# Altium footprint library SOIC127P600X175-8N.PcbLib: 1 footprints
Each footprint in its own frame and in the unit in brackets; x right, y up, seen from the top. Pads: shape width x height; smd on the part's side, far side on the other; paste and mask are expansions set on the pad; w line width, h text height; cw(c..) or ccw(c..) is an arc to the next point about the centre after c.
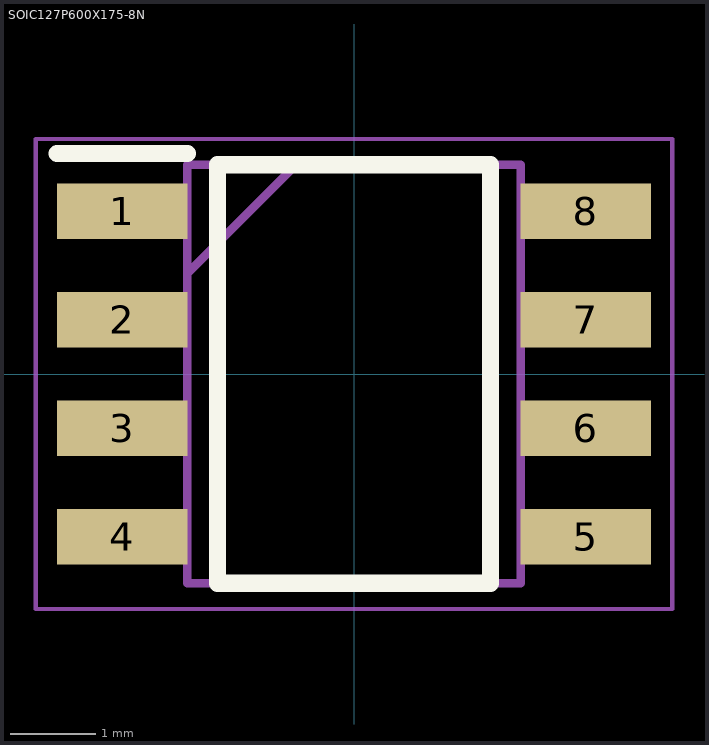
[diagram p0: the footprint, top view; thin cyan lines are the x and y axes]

## SOIC127P600X175-8N [mm]
pads (8):
  rect 1.525x0.65 smd: 1(-2.712,1.905) 2(-2.712,0.635) 3(-2.712,-0.635) 4(-2.712,-1.905) 5(2.712,-1.905) 6(2.712,-0.635) 7(2.712,0.635) 8(2.712,1.905)
Top Overlay:
  lines w0.2: -3.475,2.58 -1.95,2.58 ; -1.6,-2.45 1.6,-2.45 1.6,2.45 -1.6,2.45 -1.6,-2.45
Mechanical 15:
  lines w0.1: -1.95,1.18 -0.68,2.45 ; -1.95,-2.45 1.95,-2.45 1.95,2.45 -1.95,2.45 -1.95,-2.45
Mechanical 20:
  lines w0.05: -3.725,-2.75 3.725,-2.75 3.725,2.75 -3.725,2.75 -3.725,-2.75
3D body "IS66WVS2M8ALL-104NLI.stp": height 5.8, standoff -4.65, extent -10,-3.376 10,3.376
